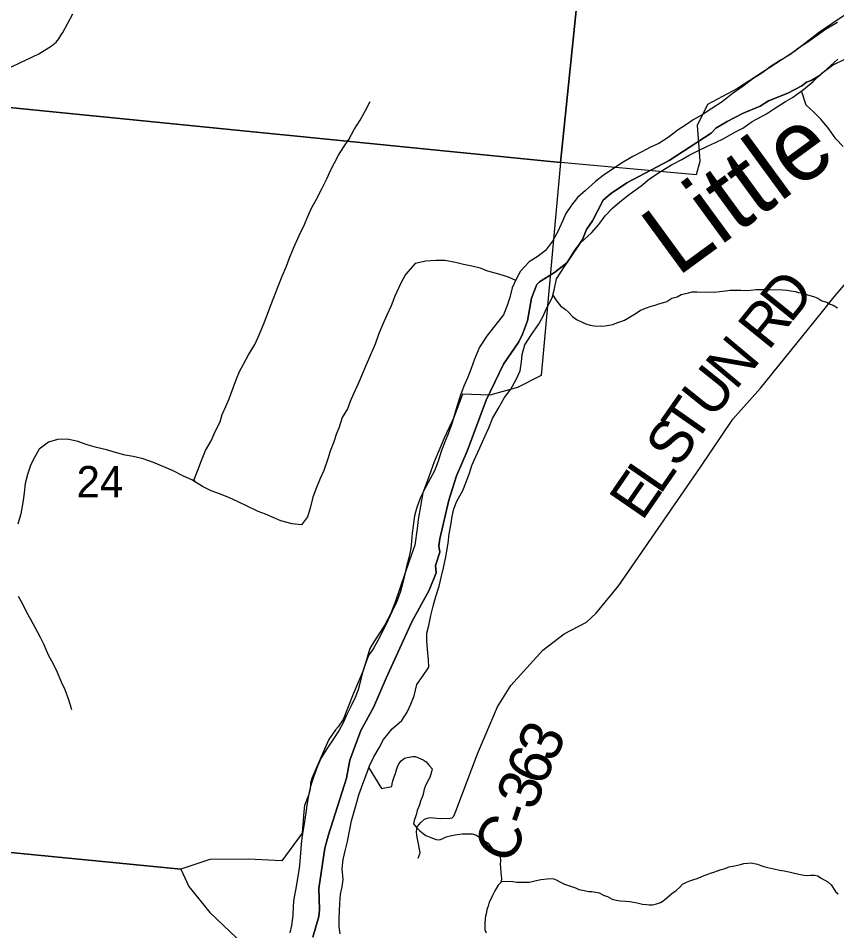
# Model space of a CAD drawing. Extents: x 0 to 34, y 0 to 22.
# Drawn here: x 2.777 to 3.323, y 16.466 to 17.075 of the extents above; entities that cross this region are included whole.
import ezdxf

# ---------------------------------------------------------------- set-up
doc = ezdxf.new("R2010")
doc.units = 0
for name, color, linetype in [('GM_X_Corporation', 7, 'Continuous'), ('GM_X_County_Road', 7, 'Continuous'), ('GM_X_County_Road_Text', 7, 'Continuous'), ('GM_X_Major_River', 7, 'Continuous'), ('GM_X_Major_River_Text', 7, 'Continuous'), ('GM_X_Minor_River', 7, 'Continuous'), ('GM_X_Section', 7, 'Continuous'), ('GM_X_Section_Text', 7, 'Continuous')]:
    doc.layers.add(name, color=color, linetype=linetype)

msp = doc.modelspace()

# ---------------------------------------------------------------- linework, layer by layer
at = {"layer": 'GM_X_Corporation'}
for points in [[(3.3236, 17.04772), (3.31163, 17.03699), (3.30577, 17.03333), (3.30251, 17.03231), (3.29952, 17.02978), (3.29017, 17.025), (3.27716, 17.01974), (3.27161, 17.01623), (3.25998, 17.01145), (3.24966, 17.00603), (3.24209, 17.00164), (3.23895, 16.99818), (3.21105, 16.98014), (3.18278, 16.96511), (3.17189, 16.95785), (3.167, 16.95348), (3.15983, 16.93984), (3.15592, 16.93411), (3.15323, 16.9273), (3.14261, 16.91172), (3.13457, 16.90536), (3.12447, 16.89912), (3.1228, 16.8973), (3.11905, 16.88814), (3.11658, 16.87309), (3.11318, 16.86434), (3.11068, 16.85909), (3.10044, 16.84423), (3.08889, 16.82017), (3.0763, 16.78613), (3.06919, 16.76968), (3.06407, 16.75359), (3.05806, 16.72783), (3.05735, 16.72299), (3.05804, 16.71893), (3.05516, 16.70991), (3.05548, 16.70503), (3.0508, 16.69349), (3.03934, 16.67243), (3.02213, 16.63485), (3.01377, 16.61525), (3.00529, 16.59983), (2.99807, 16.58009), (2.99564, 16.56807), (2.98372, 16.53042), (2.98131, 16.52157), (2.97723, 16.49455), (2.97775, 16.48066), (2.97725, 16.4759), (2.97338, 16.46205)], [(2.97338, 16.46205), (2.97725, 16.4759), (2.97775, 16.48066), (2.97723, 16.49455), (2.98131, 16.52157), (2.98372, 16.53042), (2.99564, 16.56807), (2.99807, 16.58009), (3.00529, 16.59983), (3.01377, 16.61525), (3.02213, 16.63485), (3.03934, 16.67243), (3.0508, 16.69349), (3.05548, 16.70503), (3.05516, 16.70991), (3.05804, 16.71893), (3.05735, 16.72299), (3.05806, 16.72783), (3.06407, 16.75359), (3.06919, 16.76968), (3.0763, 16.78613), (3.08889, 16.82017), (3.10044, 16.84423), (3.11068, 16.85909), (3.11318, 16.86434), (3.11658, 16.87309), (3.11905, 16.88814), (3.1228, 16.8973), (3.12447, 16.89912), (3.13457, 16.90536), (3.14261, 16.91172), (3.15323, 16.9273), (3.15592, 16.93411), (3.15983, 16.93984), (3.167, 16.95348), (3.17189, 16.95785), (3.18278, 16.96511), (3.21105, 16.98014), (3.23895, 16.99818), (3.24209, 17.00164), (3.24966, 17.00603), (3.25998, 17.01145), (3.27161, 17.01623), (3.27716, 17.01974), (3.29017, 17.025), (3.29952, 17.02978), (3.30251, 17.03231), (3.30577, 17.03333), (3.31163, 17.03699), (3.3236, 17.04772)]]:
    msp.add_lwpolyline(points, dxfattribs=at)
at = {"layer": 'GM_X_County_Road'}
for points in [[(2.59839, 16.94971), (2.59853, 16.95017), (2.60026, 16.95349), (2.60159, 16.95562), (2.60345, 16.95868), (2.60825, 16.9631), (2.61221, 16.96612), (2.6166, 16.96864), (2.79062, 17.0511), (2.79884, 17.05628), (2.80199, 17.05894), (2.80383, 17.06114), (2.80551, 17.06375), (2.80643, 17.06546), (2.81313, 17.07782)], [(3.31229, 16.87832), (3.32098, 16.8891), (3.35171, 16.92498), (3.35292, 16.92616), (3.35571, 16.92798), (3.35865, 16.92949), (3.3636, 16.93111), (3.36759, 16.93202), (3.37312, 16.93236), (3.37857, 16.93204), (3.39728, 16.92911), (3.43899, 16.91958), (3.46371, 16.91334), (3.46479, 16.9133), (3.46579, 16.91336), (3.46712, 16.91367), (3.4679, 16.91408), (3.4724, 16.91645)], [(3.04358, 16.5148), (3.04483, 16.51836), (3.04387, 16.52446), (3.04271, 16.52999), (3.04239, 16.53253), (3.04257, 16.53445), (3.04316, 16.53583), (3.04523, 16.53863), (3.04776, 16.54084), (3.0495, 16.54158), (3.05138, 16.54187), (3.05837, 16.54128), (3.06488, 16.54146), (3.06621, 16.54181), (3.06675, 16.54213), (3.06732, 16.54292), (3.06874, 16.5461), (3.08312, 16.58436), (3.09653, 16.61581), (3.10547, 16.62996), (3.1268, 16.65361), (3.14094, 16.66438), (3.15575, 16.67229), (3.16218, 16.67817), (3.1773, 16.69668), (3.23187, 16.77548), (3.25345, 16.80746), (3.27186, 16.82815), (3.31229, 16.87832)]]:
    msp.add_lwpolyline(points, dxfattribs=at)
at = {"layer": 'GM_X_Major_River'}
for points in [[(3.32325, 17.07198), (3.3152, 17.0674), (3.3104, 17.06388), (3.3029, 17.05853), (3.29715, 17.05504), (3.29138, 17.05059), (3.28525, 17.04692), (3.27834, 17.0425), (3.27353, 17.0388), (3.26682, 17.03457), (3.26028, 17.02957), (3.25298, 17.0244), (3.24625, 17.01922), (3.23953, 17.0148), (3.23301, 17.01056), (3.22707, 17.00708), (3.22188, 17.00357), (3.21709, 17.00044), (3.21036, 16.99545), (3.20403, 16.9914), (3.19848, 16.98885), (3.19274, 16.98574), (3.18681, 16.98282), (3.1803, 16.97897), (3.17319, 16.97417), (3.16686, 16.97012), (3.16186, 16.96604), (3.15511, 16.9601), (3.1499, 16.95527), (3.14582, 16.95023), (3.14211, 16.94479), (3.13973, 16.93952), (3.13695, 16.93312), (3.13321, 16.92617), (3.12854, 16.92), (3.12355, 16.9163), (3.1176, 16.91243), (3.11179, 16.90628), (3.10923, 16.9014), (3.10626, 16.89519), (3.10461, 16.88858), (3.10299, 16.88329), (3.10041, 16.87708), (3.09535, 16.87073), (3.08952, 16.86325), (3.08444, 16.85556), (3.08106, 16.84766), (3.07885, 16.84143), (3.07665, 16.83559), (3.07407, 16.82957), (3.07186, 16.82353), (3.06964, 16.81674), (3.06802, 16.81127), (3.06619, 16.80504), (3.06358, 16.79787), (3.06159, 16.79298), (3.05898, 16.786), (3.05696, 16.77959), (3.05436, 16.77299), (3.0518, 16.76811), (3.04846, 16.76191), (3.04491, 16.75495), (3.0425, 16.74797), (3.04107, 16.74307), (3.04018, 16.73644), (3.03951, 16.73151), (3.03921, 16.7262), (3.03873, 16.72127), (3.03728, 16.71504), (3.03584, 16.70937), (3.0346, 16.70427), (3.03335, 16.69859), (3.03151, 16.69199), (3.02911, 16.68558)], [(3.00091, 16.546), (3.00254, 16.55204), (3.00397, 16.55714), (3.00658, 16.56431), (3.00899, 16.5709), (3.01118, 16.57637), (3.01395, 16.58239), (3.01748, 16.58839), (3.02044, 16.59403), (3.02626, 16.60113), (3.03262, 16.60651), (3.03614, 16.61213), (3.03871, 16.6174), (3.04091, 16.62305), (3.04277, 16.63061), (3.04647, 16.63604), (3.05076, 16.64222), (3.05048, 16.64697), (3.04968, 16.65402), (3.04923, 16.65991), (3.04933, 16.66485), (3.05057, 16.66995), (3.05203, 16.67657), (3.05348, 16.68281), (3.05532, 16.68922), (3.05754, 16.69621), (3.05898, 16.70206), (3.06044, 16.70849), (3.06191, 16.71568), (3.06361, 16.72476), (3.06431, 16.73101), (3.06537, 16.73688), (3.06624, 16.74256), (3.0673, 16.74785), (3.06929, 16.75294), (3.07341, 16.75988), (3.07541, 16.76516), (3.07781, 16.77157), (3.07924, 16.77667), (3.08202, 16.78269), (3.0846, 16.78852), (3.08835, 16.79642), (3.09073, 16.80169), (3.09314, 16.8081), (3.09706, 16.81486), (3.10118, 16.82199), (3.10527, 16.8276), (3.109, 16.83399), (3.11158, 16.83982), (3.11246, 16.84588), (3.11293, 16.85062), (3.11477, 16.85704), (3.11926, 16.86397), (3.12376, 16.87072), (3.1267, 16.87579), (3.12908, 16.88125), (3.13302, 16.88857), (3.13425, 16.89349), (3.13573, 16.90105), (3.14453, 16.91455), (3.14805, 16.92018), (3.15194, 16.92522), (3.15927, 16.93191), (3.16411, 16.93732), (3.1684, 16.94312), (3.17323, 16.94815), (3.17805, 16.95242), (3.18421, 16.95743), (3.19228, 16.96315), (3.19787, 16.96778), (3.20555, 16.97295), (3.21264, 16.97717), (3.21952, 16.98064), (3.2247, 16.98377), (3.23101, 16.98687), (3.23618, 16.98942), (3.24191, 16.99215), (3.24746, 16.9947), (3.25474, 16.99892), (3.26009, 17.00166), (3.26643, 17.00609), (3.276, 17.01121), (3.28119, 17.01472), (3.28848, 17.01932), (3.29327, 17.02207), (3.30057, 17.02743), (3.30712, 17.03281), (3.31291, 17.0382), (3.32002, 17.04356), (3.32806, 17.04757)], [(3.02911, 16.68558), (3.02615, 16.67956), (3.02337, 16.67335), (3.02001, 16.66639), (3.01666, 16.66), (3.01391, 16.65512), (3.0104, 16.64987), (3.00759, 16.64215), (3.00597, 16.63705), (3.00493, 16.63213), (3.0035, 16.62704), (3.0015, 16.62195), (2.99892, 16.6163), (2.99577, 16.6101), (2.99358, 16.60502), (2.99083, 16.60014), (2.98673, 16.59376), (2.98302, 16.58833), (2.97891, 16.58177), (2.97634, 16.57612), (2.97372, 16.56877), (2.97191, 16.56349), (2.97066, 16.55763), (2.96958, 16.55138), (2.96851, 16.54495), (2.96741, 16.53775), (2.96612, 16.52999), (2.96543, 16.52412), (2.96512, 16.51805), (2.96463, 16.51274), (2.96416, 16.50782), (2.96308, 16.50138), (2.96199, 16.49457), (2.96072, 16.48776), (2.96025, 16.48302), (2.95993, 16.47657), (2.95903, 16.46994), (2.95799, 16.46502)], [(2.99149, 16.46435), (2.99083, 16.46911), (2.99075, 16.47443), (2.99103, 16.47936), (2.99133, 16.48467), (2.99183, 16.49074), (2.99288, 16.49565), (2.99355, 16.50057), (2.99294, 16.5078), (2.99344, 16.51387), (2.99488, 16.51973), (2.99633, 16.52596), (2.9978, 16.53277), (2.99908, 16.53977), (3.00091, 16.546)]]:
    msp.add_lwpolyline(points, dxfattribs=at)
at = {"layer": 'GM_X_Minor_River'}
for points in [[(3.3271, 16.98943), (3.32225, 16.99445), (3.31742, 17.00117), (3.31221, 17.00771), (3.30735, 17.01254), (3.30248, 17.01698), (3.29928, 17.02649)], [(2.89483, 16.76559), (2.8942, 16.76735), (2.89658, 16.77358), (2.89895, 16.78), (2.90171, 16.78661), (2.90542, 16.7932), (2.90817, 16.79923), (2.9115, 16.80583), (2.91291, 16.81074), (2.91527, 16.81602), (2.91744, 16.82112), (2.92021, 16.82848), (2.92239, 16.83434), (2.92436, 16.83924), (2.92709, 16.84414), (2.93042, 16.85036), (2.93451, 16.85732), (2.93687, 16.86222), (2.94041, 16.87071), (2.94239, 16.87581), (2.94517, 16.88355), (2.95031, 16.89677), (2.95288, 16.903), (2.95563, 16.9096), (2.95742, 16.91451), (2.96038, 16.92168), (2.96411, 16.92998), (2.96764, 16.93733), (2.96981, 16.94224), (2.97237, 16.94827), (2.97569, 16.9543), (2.97902, 16.96071), (2.98254, 16.96787), (2.9851, 16.97334), (2.99038, 16.98351), (2.99388, 16.98915), (2.99719, 16.99404), (3.0009, 17.00082), (3.00479, 17.00703), (3.00831, 17.01343), (3.01163, 17.01946)], [(3.1086, 16.90008), (3.10372, 16.90234), (3.0973, 16.90415), (3.08993, 16.90635), (3.08484, 16.90814), (3.07936, 16.90956), (3.07387, 16.91059), (3.06839, 16.91201), (3.06158, 16.91326), (3.05532, 16.91335), (3.04867, 16.91289), (3.04162, 16.91129), (3.03505, 16.90399), (3.03193, 16.89815), (3.028, 16.88947), (3.02543, 16.88305), (3.02267, 16.87683), (3.01973, 16.87042), (3.01716, 16.864), (3.01497, 16.85757), (3.01182, 16.85041), (3.00887, 16.84381), (3.00335, 16.8306), (3.00041, 16.82437), (2.99824, 16.81928), (2.99646, 16.81437), (2.99295, 16.80873), (2.99077, 16.8023), (2.98879, 16.7974), (2.9872, 16.79248), (2.98482, 16.78625), (2.98322, 16.78115), (2.98064, 16.7734), (2.97827, 16.76793), (2.97571, 16.76189), (2.97333, 16.75547), (2.97151, 16.74828), (2.96971, 16.74242), (2.96583, 16.73698), (2.95958, 16.73783), (2.95203, 16.73985), (2.94675, 16.74202), (2.94166, 16.74419), (2.93675, 16.74598), (2.92941, 16.74951), (2.92357, 16.75246), (2.91735, 16.7554), (2.91094, 16.75778), (2.90547, 16.75977), (2.89963, 16.76271), (2.89249, 16.767), (2.88703, 16.76955), (2.88006, 16.77308), (2.87384, 16.77584), (2.86705, 16.7786), (2.86007, 16.78099), (2.85345, 16.78262), (2.84816, 16.78365), (2.84324, 16.78487), (2.83569, 16.78707), (2.82888, 16.7887), (2.82284, 16.7905), (2.81642, 16.79269), (2.80961, 16.79413), (2.80297, 16.79404), (2.79687, 16.79224), (2.79072, 16.78759), (2.7878, 16.78251), (2.78525, 16.77742), (2.78287, 16.77062), (2.78145, 16.76475), (2.78078, 16.7585), (2.78013, 16.75338), (2.77847, 16.74448), (2.77647, 16.73748)], [(3.13344, 16.89026), (3.13582, 16.88641), (3.13858, 16.8831), (3.14174, 16.88073), (3.14378, 16.87895), (3.14655, 16.87602), (3.14915, 16.87404), (3.1529, 16.87222), (3.15534, 16.8712), (3.15836, 16.87034), (3.161, 16.8697), (3.16613, 16.86954), (3.16823, 16.86986), (3.1709, 16.87015), (3.17338, 16.87065), (3.17608, 16.87171), (3.17934, 16.87293), (3.18126, 16.87364), (3.18377, 16.87508), (3.18571, 16.87616), (3.18822, 16.87779), (3.19191, 16.88034), (3.19594, 16.88174), (3.19825, 16.88261), (3.2017, 16.88365), (3.20419, 16.88452), (3.20649, 16.88502), (3.20937, 16.88607), (3.21285, 16.88825), (3.2163, 16.88909), (3.21901, 16.89072), (3.22398, 16.8919), (3.22628, 16.8924), (3.22951, 16.89249), (3.24109, 16.89214), (3.24472, 16.8926), (3.24854, 16.89324), (3.25159, 16.89353), (3.25881, 16.8935), (3.26166, 16.89341), (3.26528, 16.89368), (3.2689, 16.89395), (3.27346, 16.894), (3.27669, 16.89409), (3.28657, 16.89379), (3.28979, 16.8935), (3.29225, 16.89305), (3.29509, 16.89277), (3.29716, 16.89195), (3.3, 16.89148), (3.30263, 16.89065), (3.30791, 16.88916), (3.31017, 16.88833), (3.31278, 16.88654), (3.31617, 16.88549), (3.31842, 16.88428), (3.3203, 16.88365), (3.32329, 16.88185)], [(2.77666, 16.68961), (2.77962, 16.68444), (2.78219, 16.67889), (2.78496, 16.6741), (2.7881, 16.66835), (2.79142, 16.66222), (2.7938, 16.65725), (2.79655, 16.65094), (2.80024, 16.64404), (2.80281, 16.63887), (2.80537, 16.63237), (2.80776, 16.62721), (2.81031, 16.62071), (2.81229, 16.61384)], [(3.01061, 16.57495), (3.01902, 16.56132), (3.02602, 16.56256), (3.02626, 16.56445), (3.02669, 16.56634), (3.02753, 16.56897), (3.02835, 16.57122), (3.02899, 16.57367), (3.02981, 16.57574), (3.03063, 16.57761), (3.03221, 16.57965), (3.03435, 16.58149), (3.03626, 16.582), (3.03989, 16.58265), (3.04179, 16.58259), (3.04386, 16.58177), (3.04686, 16.58034), (3.04892, 16.57914), (3.05112, 16.57642), (3.05278, 16.57447), (3.05253, 16.57239), (3.05128, 16.56863), (3.04948, 16.56545), (3.04826, 16.56264), (3.04763, 16.56076), (3.047, 16.5585), (3.04656, 16.55662), (3.04513, 16.55286), (3.04448, 16.55041), (3.04285, 16.54648), (3.0422, 16.54365), (3.04095, 16.53989), (3.04051, 16.53762), (3.04234, 16.53529), (3.04475, 16.53294), (3.04679, 16.53116), (3.04865, 16.52997), (3.05203, 16.52854), (3.05561, 16.52729), (3.05769, 16.52704), (3.05961, 16.52774), (3.06212, 16.52899), (3.06576, 16.53002), (3.06958, 16.53066), (3.07282, 16.53094), (3.0751, 16.53106), (3.07966, 16.53092), (3.08192, 16.53029), (3.08472, 16.52849), (3.08677, 16.5271), (3.09032, 16.5249), (3.0938, 16.52024), (3.09679, 16.51844), (3.09823, 16.51574), (3.09854, 16.51326), (3.09828, 16.51061), (3.09841, 16.50852), (3.09869, 16.50509), (3.09902, 16.50318), (3.09914, 16.5009), (3.0987, 16.49863), (3.09693, 16.49679), (3.09534, 16.49418), (3.09433, 16.49212), (3.09312, 16.48988), (3.0921, 16.48744), (3.0909, 16.48539), (3.09026, 16.48275), (3.08943, 16.4805), (3.08919, 16.47861), (3.08855, 16.47616), (3.08831, 16.47426), (3.08803, 16.47142), (3.08797, 16.46934), (3.0881, 16.46706), (3.08899, 16.46494)], [(3.09886, 16.49946), (3.1067, 16.49934), (3.10935, 16.49888), (3.11485, 16.49871), (3.1179, 16.49881), (3.12039, 16.49949), (3.12536, 16.50048), (3.12956, 16.50111), (3.13146, 16.50124), (3.13412, 16.50097), (3.13599, 16.50016), (3.13805, 16.49895), (3.14124, 16.49753), (3.14312, 16.4969), (3.14594, 16.49587), (3.14839, 16.49503), (3.15083, 16.49382), (3.15423, 16.49315), (3.15745, 16.49267), (3.15935, 16.49261), (3.16199, 16.49215), (3.16426, 16.4917), (3.16763, 16.48989), (3.16989, 16.48925), (3.17307, 16.48744), (3.17572, 16.48679), (3.17836, 16.48633), (3.18178, 16.48623), (3.18482, 16.48595), (3.1886, 16.48526), (3.19048, 16.48483), (3.19313, 16.48418), (3.19578, 16.48391), (3.19767, 16.48366), (3.19996, 16.48378), (3.20244, 16.48427), (3.20513, 16.48514), (3.20707, 16.48641), (3.2092, 16.48805), (3.21271, 16.49118), (3.21562, 16.49318), (3.21816, 16.49557), (3.21993, 16.49741), (3.22244, 16.49886), (3.22474, 16.49973), (3.22743, 16.5006), (3.22973, 16.50129), (3.23223, 16.50235), (3.23435, 16.50324), (3.23627, 16.50394), (3.23857, 16.50482), (3.24068, 16.50552), (3.24318, 16.50639), (3.2451, 16.50709), (3.24836, 16.50794), (3.25086, 16.509), (3.25353, 16.50949), (3.25564, 16.51), (3.25851, 16.51067), (3.2608, 16.51117), (3.26347, 16.51147), (3.26576, 16.51159), (3.26991, 16.5107), (3.27217, 16.50987), (3.27424, 16.50924), (3.27689, 16.50859), (3.28085, 16.50771), (3.28463, 16.50684), (3.28766, 16.50637), (3.29181, 16.50548), (3.29464, 16.50482), (3.29748, 16.50417), (3.29975, 16.50372), (3.30239, 16.50326), (3.30525, 16.50355), (3.3081, 16.50347), (3.31018, 16.50302), (3.31204, 16.50164), (3.31485, 16.50022), (3.31672, 16.49902), (3.31894, 16.49706), (3.32186, 16.4926), (3.32371, 16.49103)]]:
    msp.add_lwpolyline(points, dxfattribs=at)
at = {"layer": 'GM_X_Section'}
msp.add_lwpolyline([(2.69316, 17.52707), (3.19003, 17.47982), (3.13853, 16.97867), (2.64378, 17.02814)], close=True, dxfattribs=at)
for points in [[(3.33602, 17.08237), (3.31123, 17.06568), (3.29466, 17.05278), (3.25663, 17.02802), (3.23652, 17.01747), (3.22959, 17.00342), (3.23079, 16.989), (3.23153, 16.97932), (3.22907, 16.97048), (3.13853, 16.97867), (3.19003, 17.47982), (3.42857, 17.45821)], [(2.64378, 17.02814), (3.13853, 16.97867), (3.12563, 16.83672), (3.10974, 16.82873), (3.09125, 16.82345), (3.07309, 16.82422), (3.06726, 16.80862), (3.06091, 16.79494), (3.05792, 16.78799), (3.05432, 16.77917), (3.04969, 16.76658), (3.04667, 16.7585), (3.04364, 16.74057), (3.04295, 16.73472), (3.04138, 16.72358), (3.03755, 16.71286), (3.02825, 16.68541), (3.02505, 16.67753), (3.0211, 16.66985), (3.01444, 16.65977), (3.0113, 16.65472), (3.00702, 16.64042), (3.00022, 16.62409), (2.99343, 16.60738), (2.99029, 16.60233), (2.98835, 16.60048), (2.98405, 16.59394), (2.98107, 16.58757), (2.97529, 16.57425), (2.97269, 16.56786), (2.97168, 16.56485), (2.97159, 16.56088), (2.97057, 16.5573), (2.96776, 16.54998), (2.96729, 16.54563), (2.96623, 16.53145), (2.95257, 16.51299), (2.93044, 16.51404), (2.90448, 16.51384), (2.88522, 16.50744), (2.5921, 16.53609)], [(2.54114, 15.98076), (2.5921, 16.53609), (2.88522, 16.50744), (2.89047, 16.49596), (2.90467, 16.47861), (2.93121, 16.45323)]]:
    msp.add_lwpolyline(points, dxfattribs=at)

# ---------------------------------------------------------------- texts
at = {"layer": 'GM_X_County_Road_Text'}
for s, rotation, p in [('D', 51.09123, (3.29179, 16.87081)), ('R', 51.08561, (3.27713, 16.85265)), ('N', 49.96471, (3.25515, 16.82625)), ('U', 51.35071, (3.23965, 16.80686)), ('T', 55.13015, (3.2278, 16.78982)), ('S', 55.50432, (3.21697, 16.77407)), ('L', 55.5046, (3.20494, 16.75655)), ('E', 55.5046, (3.1929, 16.73904)), ('3', 65.07129, (3.13399, 16.57778)), ('6', 67.3361, (3.12736, 16.5619)), ('3', 69.44578, (3.12132, 16.54578)), ('-', 71.05244, (3.1176, 16.53494)), ('C', 59.68386, (3.10326, 16.50921))]:
    msp.add_text(s, height=0.02841, rotation=rotation, dxfattribs=at).set_placement(p)
at = {"layer": 'GM_X_Major_River_Text'}
msp.add_text('Little', height=0.047353, rotation=36.17637, dxfattribs=at).set_placement((3.21635, 16.90201))
at = {"layer": 'GM_X_Section_Text'}
msp.add_text('24', height=0.020928, rotation=0.00001, dxfattribs=at).set_placement((2.81567, 16.75539))

doc.saveas('drawing.dxf')
